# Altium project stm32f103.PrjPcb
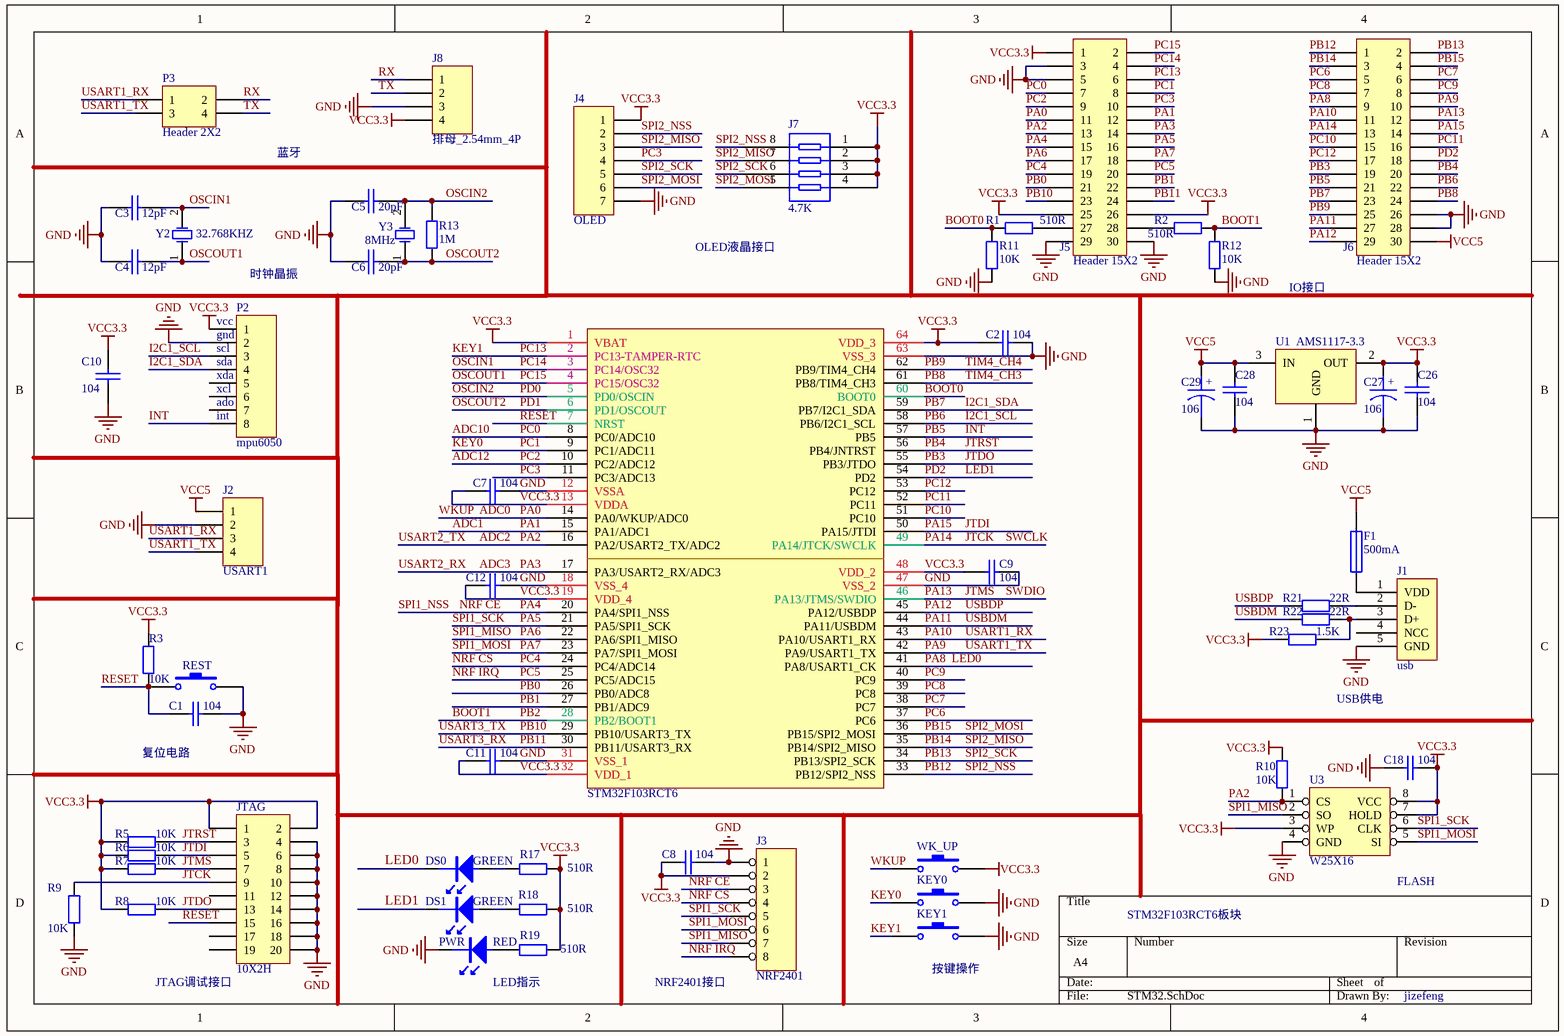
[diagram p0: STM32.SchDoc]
1 sheet, 59 parts. Net scope: global (net labels, ports and power ports of the same name join across sheets).
Board files: STM2.0.PcbDoc, STM4.0.PcbDoc

## Sheet STM32.SchDoc
size A4

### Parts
C1  value 104  [C0603]  (hidden comment: Cap_0603)
C2  value 104  [C0603]  (hidden comment: Cap_0603)
C3  value 12pF  [C0603]  (hidden comment: CAP_0603)
C4  value 12pF  [C0603]  (hidden comment: CAP_0603)
C5  value 20pF  [C0603]  (hidden comment: Cap_0603)
C6  value 20pF  [C0603]  (hidden comment: Cap_0603)
C7  value 104  [C0603]  (hidden comment: Cap_0603)
C8  value 104  [C0603]  (hidden comment: Cap_0603)
C9  value 104  [C0603]  (hidden comment: Cap_0603)
C10  value 104  [C0603]  (hidden comment: Cap_0603)
C11  value 104  [C0603]  (hidden comment: Cap_0603)
C12  value 104  [C0603]  (hidden comment: Cap_0603)
C18  value 104  [C0603]  (hidden comment: Cap_0603)
C26  value 104  [C0603]  (hidden comment: Cap_0603)
C27  106  [LC-0805]
C28  value 104  [C0603]  (hidden comment: Cap_0603)
C29  106  [LC-0805]
DS0  GREEN  [SMD0805_LED_green]
DS1  GREEN  [SMD0805_LED_green]
F1  500mA  [FUSE_SMD1206]
J1  usb  [MINI USB]
J2  USART1  [HDR1X4]
J3  NRF2401  [HDR2X4]
J4  OLED  [HDR1X7]
J5  Header 15X2  [IDE15X2_2.54]
J6  Header 15X2  [IDE15X2_2.54]
J7  value 4.7K  [RES_0603*4]  (hidden comment: Res_0603*4)
J8  排母_2.54mm_4P  [HDR1X4]
JTAG  10X2H  [IDC20]
KEY0  轻触开关/3x6x5 耐高温 环保  [SW]  (value not drawn)
KEY1  轻触开关/3x6x5 耐高温 环保  [SW]  (value not drawn)
P2  mpu6050  [HDR1X8]
P3  Header 2X2  [HDR2X2]
PWR  RED  [SMD0805_LED_green]
R1  value 510R  [Res_0603]  (hidden comment: Res_0603)
R2  value 510R  [Res_0603]  (hidden comment: Res_0603)
R3  value 10K  [Res_0603]  (hidden comment: Res_0603)
R5  value 10K  [Res_0603]  (hidden comment: Res_0603)
R6  value 10K  [Res_0603]  (hidden comment: Res_0603)
R7  value 10K  [Res_0603]  (hidden comment: Res_0603)
R8  value 10K  [Res_0603]  (hidden comment: Res_0603)
R9  value 10K  [Res_0603]  (hidden comment: Res_0603)
R10  value 10K  [Res_0603]  (hidden comment: Res_0603)
R11  value 10K  [Res_0603]  (hidden comment: Res_0603)
R12  value 10K  [Res_0603]  (hidden comment: Res_0603)
R13  value 1M  [Res_0603]  (hidden comment: Res_0603)
R17  value 510R  [Res_0603]  (hidden comment: Res_0603)
R18  value 510R  [Res_0603]  (hidden comment: Res_0603)
R19  value 510R  [Res_0603]  (hidden comment: Res_0603)
R21  value 22R  [Res_0603]  (hidden comment: Res_0603)
R22  value 22R  [Res_0603]  (hidden comment: Res_0603)
R23  value 1.5K  [Res_0603]  (hidden comment: Res_0603)
REST  轻触开关/3x6x5 耐高温 环保  [SW]  (value not drawn)
U0  STM32F103RCT6  [LQFP64]
U1  AMS1117-3.3  [LC-SOT-223]
U3  W25X16  [LC-SOP-8_208mil]
WK_UP  轻触开关/3x6x5 耐高温 环保  [SW]  (value not drawn)
Y2  value 32.768KHZ  [TC-26]  (hidden comment: 32.768KHZ±20ppm)
Y3  value 8MHz  [49SMD]  (hidden comment: 49SMD)

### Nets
GND: C1.2 C2.2 C3.1 C4.1 C5.1 C6.2 C7.2 C8.2 C9.2 C10.1 C11.2 C12.2 C18.1 C26.2 C27.2 C28.2 C29.2 J1.5(GND) J2.2 J3.1 J4.7 J5.3 J5.5 J5.29 J5.30 J6.26 J6.28 J8.3 JTAG.4 JTAG.6 JTAG.8 JTAG.10 JTAG.12 JTAG.14 JTAG.16 JTAG.18 JTAG.20 KEY0.2 KEY1.2 P2.2 PWR.K R9.1 R11.1 R12.1 REST.2 U0.12(VSSA) U0.18(VSS_4) U0.31(VSS_1) U0.47(VSS_2) U0.63(VSS_3) U1.1(GND) U3.4(GND)
VCC3.3: C2.1 C7.1 C8.1 C9.1 C10.2 C11.1 C12.1 C18.2 C26.1 C27.1 J3.2 J4.1 J5.1 J5.25 J5.26 J7.1 J7.2 J7.3 J7.4 J8.4 JTAG.1 JTAG.2 P2.1 R3.2 R5.1 R6.1 R7.1 R8.1 R10.2 R17.2 R18.2 R19.2 R23.1 U0.1(VBAT) U0.13(VDDA) U0.19(VDD_4) U0.32(VDD_1) U0.48(VDD_2) U0.64(VDD_3) U1.2(OUT) U3.3(WP) U3.7(HOLD) U3.8(VCC) WK_UP.2
VCC5: C28.1 C29.1 F1.1 J2.1 J6.30 U1.3(IN)
ADC0: J5.11 U0.14(PA0/WKUP/ADC0) WK_UP.1  [also labelled PA0, WKUP]
ADC1: J5.12 U0.15(PA1/ADC1)  [also labelled PA1]
ADC2: J5.13 R10.1 U0.16(PA2/USART2_TX/ADC2) U3.1(CS)  [also labelled PA2, USART2_TX]
ADC3: J5.14 U0.17(PA3/USART2_RX/ADC3)  [also labelled PA3, USART2_RX]
ADC10: J5.7 U0.8(PC0/ADC10)  [also labelled PC0]
ADC12: J5.9 U0.10(PC2/ADC12)  [also labelled PC2]
BOOT0: R1.1 R11.2 U0.60(BOOT0)
BOOT1: R2.2 R12.2 U0.28(PB2/BOOT1)  [also labelled PB2]
I2C1_SCL: J6.22 P2.3 U0.58(PB6/I2C1_SCL)  [also labelled PB6]
I2C1_SDA: J6.23 P2.4 U0.59(PB7/I2C1_SDA)  [also labelled PB7]
INT: J6.21 P2.8 U0.57(PB5)  [also labelled PB5]
JTCK: J6.13 JTAG.9 R9.2 U0.49(PA14/JTCK/SWCLK)  [also labelled PA14, SWCLK]
JTDI: J6.14 JTAG.5 R6.2 U0.50(PA15/JTDI)  [also labelled PA15]
JTDO: J6.19 JTAG.13 R8.2 U0.55(PB3/JTDO)  [also labelled PB3]
JTMS: J6.12 JTAG.7 R7.2 U0.46(PA13/JTMS/SWDIO)  [also labelled PA13, SWDIO]
JTRST: J6.20 JTAG.3 R5.2 U0.56(PB4/JNTRST)  [also labelled PB4]
KEY0: J5.8 KEY0.1 U0.9(PC1/ADC11)  [also labelled PC1]
KEY1: J5.6 KEY1.1 U0.2(PC13-TAMPER-RTC)  [also labelled PC13]
LED0: DS0.K J6.9 U0.41(PA8/USART1_CK)  [also labelled PA8]
LED1: DS1.K J6.18 U0.54(PD2)  [also labelled PD2]
NRF CE: J3.3 J5.15 U0.20(PA4/SPI1_NSS)  [also labelled PA4, SPI1_NSS]
NRF CS: J3.4 J5.19 U0.24(PC4/ADC14)  [also labelled PC4]
NRF IRQ: J3.8 J5.20 U0.25(PC5/ADC15)  [also labelled PC5]
OSCIN1: C3.2 J5.4 U0.3(PC14/OSC32) Y2.2(OSC2)  [also labelled PC14]
OSCIN2: C5.2 R13.2 U0.5(PD0/OSCIN) Y3.2  [also labelled PD0]
OSCOUT1: C4.2 J5.2 U0.4(PC15/OSC32) Y2.1(OSC1)  [also labelled PC15]
OSCOUT2: C6.1 R13.1 U0.6(PD1/OSCOUT) Y3.1(OSC1)  [also labelled PD1]
PA5: J3.5 J5.16 U0.21(PA5/SPI1_SCK) U3.6(CLK)  [also labelled SPI1_SCK]
PA6: J3.7 J5.17 U0.22(PA6/SPI1_MISO) U3.2(SO)  [also labelled SPI1_MISO]
PA7: J3.6 J5.18 U0.23(PA7/SPI1_MOSI) U3.5(SI)  [also labelled SPI1_MOSI]
PA9: J2.4 J6.10 P3.3 U0.42(PA9/USART1_TX)  [also labelled USART1_TX]
PA10: J2.3 J6.11 P3.1 U0.43(PA10/USART1_RX)  [also labelled USART1_RX]
PA11: J6.27 R22.1 U0.44(PA11/USBDM)  [also labelled USBDM]
PA12: J6.29 R21.1 U0.45(PA12/USBDP)  [also labelled USBDP]
PB0: J5.21 U0.26(PB0/ADC8)
PB1: J5.22 U0.27(PB1/ADC9)
PB8: J6.24 U0.61(PB8/TIM4_CH3)  [also labelled TIM4_CH3]
PB9: J6.25 U0.62(PB9/TIM4_CH4)  [also labelled TIM4_CH4]
PB10: J5.23 U0.29(PB10/USART3_TX)  [also labelled USART3_TX]
PB11: J5.24 U0.30(PB11/USART3_RX)  [also labelled USART3_RX]
PB12: J4.2 J6.1 J7.8 U0.33(PB12/SPI2_NSS)  [also labelled SPI2_NSS]
PB13: J4.5 J6.2 J7.6 U0.34(PB13/SPI2_SCK)  [also labelled SPI2_SCK]
PB14: J4.3 J6.3 J7.7 U0.35(PB14/SPI2_MISO)  [also labelled SPI2_MISO]
PB15: J4.6 J6.4 J7.5 U0.36(PB15/SPI2_MOSI)  [also labelled SPI2_MOSI]
PC3: J4.4 J5.10 U0.11(PC3/ADC13)
PC6: J6.5 U0.37(PC6)
PC7: J6.6 U0.38(PC7)
PC8: J6.7 U0.39(PC8)
PC9: J6.8 U0.40(PC9)
PC10: J6.15 U0.51(PC10)
PC11: J6.16 U0.52(PC11)
PC12: J6.17 U0.53(PC12)
RESET: C1.1 JTAG.15 R3.1 REST.1 U0.7(NRST)
RX: J8.1 P3.2
TX: J8.2 P3.4
NetDS0_A: DS0.A R17.1
NetDS1_A: DS1.A R18.1
NetF1_2: F1.2 J1.1(VDD)
NetJ1_2: J1.2(D-) R21.2
NetJ1_3: J1.3(D+) R22.2 R23.2
NetJ5_27: J5.27 R1.2
NetJ5_28: J5.28 R2.1
NetPWR_A: PWR.A R19.1

Not connected (* = marked no-connect by the designer): J1 4(NCC); JTAG 11 17 19; P2 5 6 7

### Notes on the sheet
- 蓝牙
- OLED液晶接口
- 时钟晶振
- IO接口
- (near P2) vcc
- (near P2) gnd
- (near P2) scl
- (near P2) sda
- (near P2) xda
- (near P2) xcl
- (near P2) ado
- (near P2) int
- USB供电
- 复位电路
- STM32F103RCT6板块
- (near U3) FLASH
- (near JTAG) JTAG调试接口
- LED指示
- (near J3) NRF2401接口
- (near KEY1) 按键操作
- jizefeng

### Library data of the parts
C1 C2 C7 C9 C11 C12 = 100nF_C0603_27010084: 贴片电容，100nF/50V，±10%，SMD0603，SAMSUNG; 货位: 080608
C3 C4 = 15pF_C0603_27010002: 贴片电容，15pF/50V，±5%，SMD0603，SAMSUNG; 货位: 080102
C5 C6 = 22pF_C0603_27010004: 贴片电容，22pF/50V，±5%，SMD0603，SAMSUNG; 货位: 080104
C8 C10 C18 C26 C28 = 0.1uF_C0603_27010044: 贴片电容，0.1uF/50V，±10%，SMD0603，SAMSUNG; 货位: 080604
C27 C29 = CAPACITOR POL: Capacitor
DS0 DS1 PWR = LED绿色: 发光二极管，绿色，SMD0805，国产; ID: 24040001; 货位: 011601
F1 = NANOSMDC050F/13.2V-2: 贴片保险丝，NANOSMDC050F/13.2V-2,500MA，SMD1206，NANO; ID: 29020001; 货位: 081901
J2 J8 = 排母_2.54mm_4P: 排母，间距2.54mm，1*4P，直插，国产; ID: 31090003; 货位: 1010
J3 = HEADER 8: 8 Pin Header
J4 = Header 7: 排母, 7-Pin,2.54MM; Value: Header
J5 J6 = Header 15X2: Header, 15-Pin, Dual row
J7 = 4.7K_0603*4_26050008: 电阻排，4.7K±5%，1/16W，0603*4，厚声; 货位: 072005
JTAG = Header 10X2H: Header, 10-Pin, Dual row, Right Angle
KEY0 KEY1 REST WK_UP = 轻触开关: ID: 32010002; 货位: 010708
P2 = MHDR1X8: Header, 8-Pin
P3 = Header 2X2: Header, 2-Pin, Dual row
R1 R2 R17-R19 = 510R_0603_26020037: 贴片电阻，510R±1%，1/10W，SMD0603，厚声; 货位: 070505
R3 R10 = 10K_0603_26020076: 贴片电阻，10K±0.1%，1/10W，SMD0603，厚声; 货位: 071004
R5-R9 R11 R12 = 10K_0603_26020077: 贴片电阻，10K±1%，1/10W，SMD0603，厚声; 货位: 071005
R13 = 1M_0603_26020140: 贴片电阻，1M±1%，1/10W，SMD0603，RALEC; 货位: 071804
R21 R22 = 22R_0603_26020015: 贴片电阻，22R±1%，1/10W，SMD0603，RALEC; 货位: 070207
R23 = 1.5K_0603_26020049: 贴片电阻，1.5K±1%，1/10W，SMD0603，RALEC; 货位: 070701
U0 = STM32F103RBT6
U1 = LT1085CM-3.3
Y2 = 32.768KHZ±20ppm: 无源晶振，32.768KHZ±20ppm，TC-26，插件，2*6mm，国产; ID: 25040001; 货位: 011805
Y3 = 8MHz±20PPm_49SMD_25010002: 49SMD，8MHz±20PPm，49SMD，LC; 货位: 011802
